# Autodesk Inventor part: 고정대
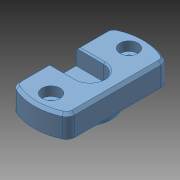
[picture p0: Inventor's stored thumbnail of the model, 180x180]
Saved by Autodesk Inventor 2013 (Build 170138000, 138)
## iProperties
Created: 2023-11
Part Number: 고정대
Material: 강철, 탄소
Document SubType Name: Modeling
Designer: mdu-01
Density: 1 g/cm^3
Author: mdu-01
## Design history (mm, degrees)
sketch "스케치1"
  geometry: L1 (10, -15.492)-(10, 15.492); L2 (-10, -15.492)-(-10, 15.492); A1 r 20 centre (0, 0) between (8.235, 18.226) and (-8.235, 18.226); A2 r 20 centre (0, 0) between (-8.235, -18.226) and (8.235, -18.226); A3 r 3 centre (7, -15.492) between (8.235, -18.226) and (10, -15.492); A4 r 3 centre (-7, -15.492) between (-10, -15.492) and (-8.235, -18.226); A5 r 3 centre (7, 15.492) between (10, 15.492) and (8.235, 18.226); A6 r 3 centre (-7, 15.492) between (-8.235, 18.226) and (-10, 15.492); 5 further points
  constraints: 16 point on circle, 8 tangent, 6 centre point, 4 end point, 4 point on line, 3 equal radius, 1 coincident, 1 horizontal alignment, 1 parallel, 1 vertical
  dimensions: "d1" = 20 distance between parallel lines of L2 L1; "d2" = 20 radius of A1; "d3" = 3 radius of A3; "d6" = 3 radius of A6
extrude "돌출1" new body sketch "스케치1" distance "d4" = 8; taper "d5" = 0 deg
sketch "스케치2"
  geometry: C1 r 8 at (0, 0); 1 further point
  constraints: 1 centre point, 1 coincident
  dimensions: "d7" = 16 diameter of C1
extrude "돌출2" join sketch "스케치2" distance "d8" = 4; taper "d9" = 0 deg
chamfer "모따기1" distance "d10" = 1; stored, may be unused: second distance "d11" = 2, angle "d12" = 45 deg
sketch "스케치3"
  geometry: L1 (0, 5)-(-10, 5); L2 (-10, 5)-(-10, -5); L3 (-10, -5)-(0, -5); L4 (-10, 15.492)-(-10, -15.492) reference; A1 r 5 centre (0, 0) between (0, -5) and (0, 5); 1 further point
  constraints: 6 end point, 2 horizontal, 2 point on circle, 2 tangent, 1 centre point, 1 coincident, 1 collinear, 1 perpendicular
  dimensions: "d13" = 10 diameter of A1
extrude "돌출3" cut sketch "스케치3" distance "d14" = 6; taper "d15" = 0 deg
chamfer "모따기2" distance "d16" = 0.5; stored, may be unused: second distance "d17" = 2, angle "d18" = 45 deg
sketch "스케치4"
  geometry: C1 r 1.23 at (0, 14) reference; C2 r 1.23 at (0, -14) reference; 1 further point
hole "구멍1" sketch "스케치4" at (0, 14), (0, -14) diameter "d19" = 3.4; stored, may be unused: countersink angle "d23" = 90 deg, drill point angle "d25" = 118 deg; dims "d20" = 6, "d21" = 6.5, "d22" = 5, "d24" = 8
node "솔리드1"
node "참조1"
node "참조2"
